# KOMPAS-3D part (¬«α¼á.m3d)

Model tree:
1. Эскиз:1
2. Операция выдавливания:1
     Расстояние 1 = 2; Расстояние 2 = 0.3
3. Эскиз:3
4. Операция выдавливания:3
     Расстояние 1 = 2; Расстояние 2 = 0.3
5. Скругление:2
     Радиус = 1; Хорда = 0.2
6. Скругление:3
     Радиус = 0.2; Хорда = 0.2
7. Эскиз:4
8. Вырезать элемент выдавливания:1
     Расстояние 2 = 1; Расстояние 1 = 45.3
9. Массив по сетке:1  (with: Операция выдавливания:3, Скругление:2, Скругление:3, Вырезать элемент выдавливания:1)  (labels: Экземпляр ( 1, 1 ); Экземпляр ( 2, 1 ); Экземпляр ( 3, 1 ); Экземпляр ( 4, 1 ))
     N 1 = 7; Шаг 1 = 116; Угол раствора = 90; N 2 = 1; Номер 1 = 1; Номер 2 = 1
10. Эскиз:5
11. Операция выдавливания:4
     Расстояние 1 = 1; Расстояние 2 = 1
12. Эскиз:6
13. Операция выдавливания:5
     Расстояние 1 = 2; Расстояние 2 = 1
14. Эскиз:7
15. Операция выдавливания:6
     Расстояние 1 = 1; Расстояние 2 = 1
16. Массив по концентрической сетке:1  (with: Операция выдавливания:6)  (labels: Экземпляр ( 1, 1 ); Экземпляр ( 1, 2 ); Экземпляр ( 1, 3 ); Экземпляр ( 1, 4 ))
     N 2 = 5; Шаг 2 = 360; Номер 2 = 1
17. Эскиз:9
18. Вырезать элемент выдавливания:3
     Расстояние 2 = 6.05758; Расстояние 1 = 1
19. Массив по концентрической сетке:3  (with: Вырезать элемент выдавливания:3)  (labels: Экземпляр ( 1, 1 ); Экземпляр ( 1, 2 ); Экземпляр ( 1, 3 ); Экземпляр ( 1, 4 ))
     N 2 = 5; Шаг 2 = 360; Номер 2 = 1
20. Эскиз:10
21. Операция выдавливания:7
     Расстояние 1 = 1; Расстояние 2 = 1
22. Массив по концентрической сетке:4  (with: Операция выдавливания:7)  (labels: Экземпляр ( 1, 1 ); Экземпляр ( 1, 2 ); Экземпляр ( 1, 3 ); Экземпляр ( 1, 4 ))
     N 2 = 5; Шаг 2 = 360; Номер 2 = 1
23. Скругление:4
     Радиус = 1
24. Скругление:6
     Радиус = 1
25. Скругление:7
     Радиус = 1
26. Скругление:8
     Радиус = 1
27. Эскиз:11
28. Операция выдавливания:8
     Расстояние 1 = 10
29. Эскиз:13
30. Вырезать элемент выдавливания:4
     Расстояние 1 = 106.009
31. Эскиз:14
32. Операция выдавливания:9
     Расстояние 1 = 0.5; Расстояние 2 = 1.5
33. Эскиз:15
34. Операция выдавливания:10
     Расстояние 1 = 1; Расстояние 2 = 1
35. Эскиз:16
36. Операция выдавливания:11
     Расстояние 1 = 1; Расстояние 2 = 1
37. Эскиз:17
38. Вырезать элемент выдавливания:5
     Расстояние 1 = 3
39. Эскиз:18
40. Операция выдавливания:12
     Расстояние 1 = 1; Расстояние 2 = 1

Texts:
  Сплав АЛ8  ГОСТ 1583-93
